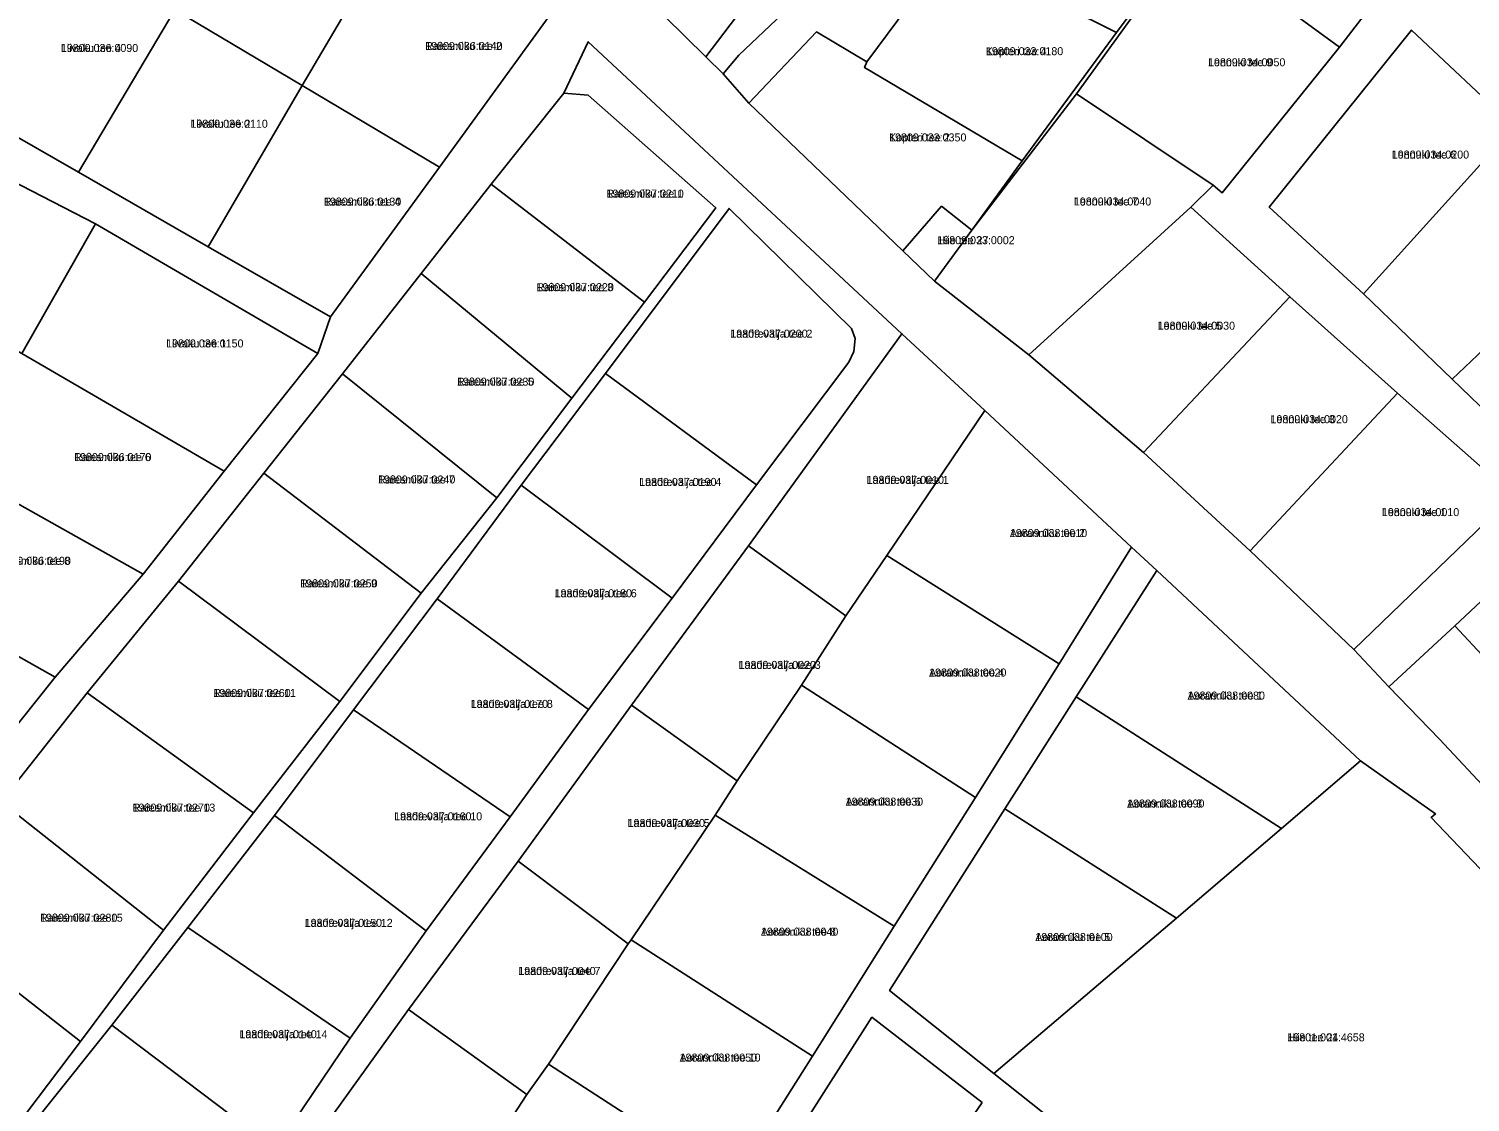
# Model space of a CAD drawing. Extents: x 516875 to 535633, y 6574491 to 6593094.
# Drawn here: x 521221.7 to 521492, y 6587952 to 6588153.3 of the extents above; entities that cross this region are included whole.
import ezdxf

# ---------------------------------------------------------------- set-up
doc = ezdxf.new("R2010")
doc.units = 0
for name, color, linetype in [('L_AADRESS', 7, 'Continuous'), ('PIIR', 7, 'Continuous'), ('TUNNUS', 7, 'Continuous')]:
    doc.layers.add(name, color=color, linetype=linetype)

msp = doc.modelspace()

# ---------------------------------------------------------------- linework, layer by layer
at = {"layer": 'PIIR'}
for points in [[(521017.6, 6588315.56), (521041.3, 6588310.85), (521161.97, 6588248.41), (521164, 6588251.13), (521249.19, 6588215.21), (521251.74, 6588208.19), (521261.65, 6588203.54), (521269.05, 6588200.08), (521301.38, 6588180.99), (521317.52, 6588171.31), (521334.28, 6588161.25), (521337.07, 6588159.57), (521348.67, 6588148.07), (521351.93, 6588144.84), (521356.73, 6588139.38), (521385.64, 6588111.65), (521391.55, 6588105.98), (521409.24, 6588092.16), (521430.76, 6588073.85), (521450.73, 6588055.41), (521470.18, 6588036.92), (521476.73, 6588029.86), (521486.21, 6588020.09), (521519.33, 6587984.61)], [(521158.93, 6587943.85), (521180.61, 6587971.98), (521193.57, 6587989.19), (521210.46, 6588011.39), (521226.67, 6588031.69), (521243.16, 6588051), (521258.36, 6588070.34), (521275.91, 6588092.39), (521278.32, 6588099.31), (521298.75, 6588127.37), (521319.09, 6588155.45), (521290.81, 6588172.96), (521266.84, 6588187.34), (521242.95, 6588201.16), (521217.86, 6588215.37), (521191.59, 6588226.05), (521158.76, 6588238.82), (521154.23, 6588241.17), (521121.69, 6588257.97), (521102.37, 6588267.78), (521050.16, 6588294.72), (521045.07, 6588297.27), (521040.82, 6588299.53), (521002.53, 6588304.56)], [(521540.83, 6588089.77), (521489.11, 6588041.31), (521476.73, 6588029.86), (521470.18, 6588036.92), (521500.13, 6588065.78), (521478.34, 6588084.96), (521458.19, 6588103.05), (521439.62, 6588119.88), (521443.81, 6588124.01), (521445.49, 6588122.56), (521467.47, 6588149.88), (521488.12, 6588176.69), (521508.12, 6588202.69)], [(521394.5, 6588168.18), (521378.85, 6588147.09), (521369.43, 6588152.73), (521356.73, 6588139.38), (521351.93, 6588144.84), (521354.89, 6588148.37), (521363.04, 6588156.13)], [(521500.27, 6588134.95), (521481, 6588153.08), (521454.29, 6588119.88), (521471.99, 6588103.62), (521488.58, 6588087.62), (521505.71, 6588071.1)], [(521514.67, 6587973.91), (521484.65, 6588005.35), (521485.51, 6588006.06), (521471.41, 6588015.99), (521433.21, 6588051.72), (521428.49, 6588056.06), (521400.98, 6588081.73), (521385.44, 6588096.11), (521326.62, 6588150.87), (521322.04, 6588141.26), (521308.43, 6588124.17), (521295.33, 6588107.43), (521280.58, 6588088.62), (521265.78, 6588069.94), (521249.81, 6588049.72), (521232.68, 6588028.77), (521216.57, 6588008.3), (521200.27, 6587987.77), (521181.69, 6587964.04), (521164.92, 6587943.01)], [(521215.28, 6587942.14), (521231.42, 6587963.35), (521246.97, 6587984.22), (521263.88, 6588006.26), (521280.05, 6588027.13), (521295.3, 6588047.44), (521309.48, 6588065.34), (521323.53, 6588084.02), (521337.18, 6588102.04), (521350.56, 6588119.72), (521326.59, 6588140.87), (521322.04, 6588141.26), (521326.62, 6588150.87), (521385.44, 6588096.11), (521356.66, 6588056.35), (521334.72, 6588026.42), (521313.46, 6587997.16), (521292.9, 6587969.35), (521274.13, 6587943.17)], [(521138.98, 6587940.98), (521137.6, 6587971.07), (521136.28, 6588000.92), (521134.56, 6588030.83), (521132.41, 6588064.75), (521158.39, 6588098), (521171.42, 6588121.81), (521183.95, 6588143.81), (521193.2, 6588147.93), (521206.39, 6588140.55), (521231.05, 6588126.44), (521255.39, 6588112.43), (521278.32, 6588099.31), (521275.91, 6588092.39), (521234.23, 6588116.76), (521190.3, 6588139.35), (521178.02, 6588117.45), (521165.86, 6588095.28), (521153.98, 6588073.57), (521141.75, 6588051.55), (521141.82, 6588020.03), (521142.39, 6587992.23), (521145.81, 6587956.49), (521147.96, 6587948.67)], [(521267.98, 6587943.22), (521281.97, 6587963.99), (521296.27, 6587984.13), (521311.97, 6588005.48), (521326.68, 6588025.64), (521342.39, 6588046.49), (521358.19, 6588067.75), (521375.48, 6588090.78), (521376.44, 6588092.78), (521376.68, 6588095.2), (521376.01, 6588097.08), (521353.02, 6588119.61), (521329.85, 6588088.65), (521314.08, 6588067.74), (521298.31, 6588046.39), (521282.64, 6588025.58), (521267.79, 6588005.75), (521251.54, 6587984.76), (521237.28, 6587966.42), (521224.36, 6587950.23)], [(521353.63, 6587936.77), (521368.68, 6587960.59), (521383.97, 6587985.03), (521399.21, 6588009.13), (521414.9, 6588034.22), (521428.49, 6588056.06), (521433.21, 6588051.72), (521418.12, 6588028.01), (521404.73, 6588007.03), (521383.13, 6587972.91), (521402.67, 6587957.39), (521442.87, 6587925.41)], [(521400.47, 6587951.9), (521379.8, 6587967.93), (521355.54, 6587929.86)]]:
    msp.add_lwpolyline(points, dxfattribs=at)
for points in [[(521488.12, 6588176.69), (521467.47, 6588149.88), (521439.37, 6588170.42), (521453.71, 6588190.56), (521459.29, 6588197.98)], [(521290.81, 6588172.96), (521273.02, 6588142.68), (521249.1, 6588156.87), (521266.84, 6588187.34)], [(521440.2, 6588172.11), (521425.69, 6588152.61), (521394.5, 6588168.18), (521409.1, 6588187.6)], [(521319.09, 6588155.45), (521298.75, 6588127.37), (521273.02, 6588142.68), (521290.81, 6588172.96)], [(521347.85, 6588171.73), (521344.77, 6588166.29), (521350.63, 6588162.97), (521353.71, 6588168.4), (521360.97, 6588164.28), (521348.67, 6588148.07), (521337.07, 6588159.57), (521334.28, 6588161.25), (521343.47, 6588173.7)], [(521249.1, 6588156.87), (521231.05, 6588126.44), (521206.39, 6588140.55), (521225.06, 6588171.18)], [(521467.47, 6588149.88), (521445.49, 6588122.56), (521443.81, 6588124.01), (521418.19, 6588141.14), (521439.37, 6588170.42)], [(521425.69, 6588152.61), (521408, 6588128.54), (521378.45, 6588146.05), (521378.85, 6588147.09), (521394.5, 6588168.18)], [(521364.05, 6588161.68), (521363.04, 6588156.13), (521354.89, 6588148.37), (521351.93, 6588144.84), (521348.67, 6588148.07), (521360.97, 6588164.28)], [(521273.02, 6588142.68), (521255.39, 6588112.43), (521231.05, 6588126.44), (521249.1, 6588156.87)], [(521378.85, 6588147.09), (521378.45, 6588146.05), (521408, 6588128.54), (521398.52, 6588115.54), (521392.87, 6588120.03), (521385.64, 6588111.65), (521356.73, 6588139.38), (521369.43, 6588152.73)], [(521500.27, 6588134.95), (521471.99, 6588103.62), (521454.29, 6588119.88), (521481, 6588153.08)], [(521298.75, 6588127.37), (521278.32, 6588099.31), (521255.39, 6588112.43), (521273.02, 6588142.68)], [(521234.23, 6588116.76), (521220.42, 6588092.43), (521218.56, 6588093.45), (521178.02, 6588117.45), (521190.3, 6588139.35)], [(521322.04, 6588141.26), (521326.59, 6588140.87), (521350.56, 6588119.72), (521337.18, 6588102.04), (521308.43, 6588124.17)], [(521443.81, 6588124.01), (521439.62, 6588119.88), (521409.24, 6588092.16), (521391.55, 6588105.98), (521398.52, 6588115.54), (521418.19, 6588141.14)], [(521506.61, 6588128.99), (521519.5, 6588116.86), (521488.58, 6588087.62), (521471.99, 6588103.62), (521500.27, 6588134.95)], [(521308.43, 6588124.17), (521337.18, 6588102.04), (521323.53, 6588084.02), (521295.33, 6588107.43)], [(521353.02, 6588119.61), (521376.01, 6588097.08), (521376.68, 6588095.2), (521376.44, 6588092.78), (521375.48, 6588090.78), (521358.19, 6588067.75), (521329.85, 6588088.65)], [(521398.52, 6588115.54), (521391.55, 6588105.98), (521385.64, 6588111.65), (521392.87, 6588120.03)], [(521458.19, 6588103.05), (521430.76, 6588073.85), (521409.24, 6588092.16), (521439.62, 6588119.88)], [(521275.91, 6588092.39), (521258.36, 6588070.34), (521220.42, 6588092.43), (521234.23, 6588116.76)], [(521537.69, 6588100.14), (521534.98, 6588097.54), (521505.71, 6588071.1), (521488.58, 6588087.62), (521519.5, 6588116.86)], [(521295.33, 6588107.43), (521323.53, 6588084.02), (521309.48, 6588065.34), (521280.58, 6588088.62)], [(521478.34, 6588084.96), (521450.73, 6588055.41), (521430.76, 6588073.85), (521458.19, 6588103.05)], [(521356.66, 6588056.35), (521385.44, 6588096.11), (521400.98, 6588081.73), (521382.59, 6588054.52), (521374.93, 6588043.23)], [(521220.42, 6588092.43), (521258.36, 6588070.34), (521243.16, 6588051), (521204.84, 6588072.5), (521218.56, 6588093.45)], [(521280.58, 6588088.62), (521309.48, 6588065.34), (521295.3, 6588047.44), (521265.78, 6588069.94)], [(521329.85, 6588088.65), (521358.19, 6588067.75), (521342.39, 6588046.49), (521314.08, 6588067.74)], [(521489.11, 6588041.31), (521540.83, 6588089.77), (521552.09, 6588077.21), (521557.57, 6588080.35), (521576.42, 6588072.76), (521587.8, 6588066.87), (521550.43, 6588019.97), (521539.48, 6588031.44), (521535.42, 6588027.5), (521529.37, 6588027.23), (521500.98, 6588028.57)], [(521500.13, 6588065.78), (521470.18, 6588036.92), (521450.73, 6588055.41), (521478.34, 6588084.96)], [(521428.49, 6588056.06), (521414.9, 6588034.22), (521382.59, 6588054.52), (521400.98, 6588081.73)], [(521204.84, 6588072.5), (521243.16, 6588051), (521226.67, 6588031.69), (521190.03, 6588052.36), (521202.42, 6588073.87)], [(521265.78, 6588069.94), (521295.3, 6588047.44), (521280.05, 6588027.13), (521249.81, 6588049.72)], [(521314.08, 6588067.74), (521342.39, 6588046.49), (521326.68, 6588025.64), (521298.31, 6588046.39)], [(521334.72, 6588026.42), (521356.66, 6588056.35), (521374.93, 6588043.23), (521366.64, 6588030.18), (521354.56, 6588012.25)], [(521414.9, 6588034.22), (521399.21, 6588009.13), (521366.64, 6588030.18), (521374.93, 6588043.23), (521382.59, 6588054.52)], [(521226.67, 6588031.69), (521210.46, 6588011.39), (521180.01, 6588029.19), (521177.09, 6588030.93), (521190.03, 6588052.36)], [(521471.41, 6588015.99), (521456.62, 6588003.29), (521418.12, 6588028.01), (521433.21, 6588051.72)], [(521249.81, 6588049.72), (521280.05, 6588027.13), (521263.88, 6588006.26), (521232.68, 6588028.77)], [(521298.31, 6588046.39), (521326.68, 6588025.64), (521311.97, 6588005.48), (521282.64, 6588025.58)], [(521476.73, 6588029.86), (521489.11, 6588041.31), (521500.98, 6588028.57), (521529.37, 6588027.23), (521535.42, 6588027.5), (521539.48, 6588031.44), (521550.43, 6588019.97), (521519.33, 6587984.61), (521486.21, 6588020.09)], [(521232.68, 6588028.77), (521263.88, 6588006.26), (521246.97, 6587984.22), (521216.57, 6588008.3)], [(521399.21, 6588009.13), (521383.97, 6587985.03), (521350.41, 6588005.82), (521354.56, 6588012.25), (521366.64, 6588030.18)], [(521334.72, 6588026.42), (521354.56, 6588012.25), (521350.41, 6588005.82), (521334.68, 6587982.43), (521334.13, 6587981.66), (521313.46, 6587997.16)], [(521456.62, 6588003.29), (521436.92, 6587986.49), (521404.73, 6588007.03), (521418.12, 6588028.01)], [(521282.64, 6588025.58), (521311.97, 6588005.48), (521296.27, 6587984.13), (521267.79, 6588005.75)], [(521456.62, 6588003.29), (521471.41, 6588015.99), (521485.51, 6588006.06), (521484.65, 6588005.35), (521514.67, 6587973.91), (521492.26, 6587947.79), (521477.81, 6587930.85), (521464.56, 6587914.78), (521461.03, 6587910.82), (521442.87, 6587925.41), (521402.67, 6587957.39), (521436.92, 6587986.49)], [(521216.57, 6588008.3), (521246.97, 6587984.22), (521231.42, 6587963.35), (521200.27, 6587987.77)], [(521436.92, 6587986.49), (521402.67, 6587957.39), (521383.13, 6587972.91), (521404.73, 6588007.03)], [(521267.79, 6588005.75), (521296.27, 6587984.13), (521281.97, 6587963.99), (521251.54, 6587984.76)], [(521383.97, 6587985.03), (521368.68, 6587960.59), (521334.68, 6587982.43), (521350.41, 6588005.82)], [(521313.46, 6587997.16), (521334.13, 6587981.66), (521319.16, 6587959.1), (521315.09, 6587953.45), (521292.9, 6587969.35)], [(521200.27, 6587987.77), (521231.42, 6587963.35), (521215.28, 6587942.14), (521181.69, 6587964.04)], [(521251.54, 6587984.76), (521281.97, 6587963.99), (521267.98, 6587943.22), (521237.28, 6587966.42)], [(521368.68, 6587960.59), (521353.63, 6587936.77), (521319.16, 6587959.1), (521334.13, 6587981.66), (521334.68, 6587982.43)], [(521292.9, 6587969.35), (521315.09, 6587953.45), (521303.38, 6587935.38), (521297.34, 6587926.82), (521274.13, 6587943.17)], [(521224.36, 6587950.23), (521237.28, 6587966.42), (521267.98, 6587943.22), (521254.61, 6587924.08), (521223.14, 6587947.9)], [(521400.47, 6587951.9), (521375.09, 6587915), (521355.54, 6587929.86), (521379.8, 6587967.93)], [(521353.63, 6587936.77), (521339.07, 6587913.66), (521303.38, 6587935.38), (521315.09, 6587953.45), (521319.16, 6587959.1)]]:
    msp.add_lwpolyline(points, close=True, dxfattribs=at)

# ---------------------------------------------------------------- texts
at = {"layer": 'L_AADRESS'}
for s, p in [('Liivaku tee 4', (521227.75, 6588148.96)), ('Raiesmiku tee 2', (521296.06, 6588149.34)), ('Kopteri tee 4', (521401.18, 6588148.36)), ('Lennuki tee 9', (521442.83, 6588146.28)), ('Liivaku tee 2', (521252.04, 6588134.75)), ('Kopteri tee 2', (521383.03, 6588132.19)), ('Lennuki tee 6', (521477.28, 6588128.97)), ('Raiesmiku tee 1', (521330.04, 6588121.65)), ('Raiesmiku tee 4', (521277.07, 6588120.15)), ('Lennuki tee 7', (521417.68, 6588120.17)), ('Hiie tee 27', (521392.08, 6588112.91)), ('Raiesmiku tee 3', (521316.93, 6588104.1)), ('Laadrevälja tee 2', (521353.27, 6588095.38)), ('Lennuki tee 5', (521433.39, 6588096.87)), ('Liivaku tee 1', (521247.49, 6588093.55)), ('Raiesmiku tee 5', (521302.02, 6588086.38)), ('Lennuki tee 3', (521454.55, 6588079.34)), ('Raiesmiku tee 6', (521230.23, 6588072.23)), ('Raiesmiku tee 7', (521287.21, 6588068.03)), ('Laadrevälja tee 4', (521336.18, 6588067.57)), ('Laadrevälja tee 1', (521378.82, 6588067.96)), ('Lennuki tee 1', (521475.43, 6588061.91)), ('Aoranniku tee 2', (521405.68, 6588057.98)), ('Raiesmiku tee 8', (521215.13, 6588052.78)), ('Raiesmiku tee 9', (521272.63, 6588048.54)), ('Laadrevälja tee 6', (521320.33, 6588046.69)), ('Laadrevälja tee 3', (521354.82, 6588033.25)), ('Aoranniku tee 4', (521390.54, 6588031.82)), ('Raiesmiku tee 11', (521256.33, 6588027.99)), ('Aoranniku tee 1', (521439, 6588027.5)), ('Laadrevälja tee 8', (521304.59, 6588025.94)), ('Raiesmiku tee 13', (521241.2, 6588006.49)), ('Aoranniku tee 6', (521374.9, 6588007.61)), ('Aoranniku tee 3', (521427.66, 6588007.25)), ('Laadrevälja tee 10', (521290.24, 6588004.85)), ('Laadrevälja tee 5', (521334.01, 6588003.6)), ('Raiesmiku tee 15', (521223.85, 6587985.83)), ('Laadrevälja tee 12', (521273.46, 6587984.87)), ('Aoranniku tee 8', (521359.01, 6587983.21)), ('Aoranniku tee 5', (521410.45, 6587982.21)), ('Laadrevälja tee 7', (521313.52, 6587975.85)), ('Laadrevälja tee 14', (521261.23, 6587963.99)), ('Hiie tee 24', (521457.7, 6587963.4)), ('Aoranniku tee 10', (521343.77, 6587959.6))]:
    msp.add_text(s, height=1.5, dxfattribs=at).set_placement(p)
at = {"layer": 'TUNNUS'}
for s, p in [('19809:036:0090', (521227.75, 6588148.96)), ('19809:036:0140', (521296.06, 6588149.34)), ('19809:033:0180', (521401.18, 6588148.36)), ('19809:034:0050', (521442.83, 6588146.28)), ('19809:036:0110', (521252.04, 6588134.75)), ('19809:033:0350', (521383.03, 6588132.19)), ('19809:034:0200', (521477.28, 6588128.97)), ('19809:037:0210', (521330.04, 6588121.65)), ('19809:036:0130', (521277.07, 6588120.15)), ('19809:034:0040', (521417.68, 6588120.17)), ('19809:033:0002', (521392.08, 6588112.91)), ('19809:037:0220', (521316.93, 6588104.1)), ('19809:037:0200', (521353.27, 6588095.38)), ('19809:034:0030', (521433.39, 6588096.87)), ('19809:036:0150', (521247.49, 6588093.55)), ('19809:037:0230', (521302.02, 6588086.38)), ('19809:034:0020', (521454.55, 6588079.34)), ('19809:036:0170', (521230.23, 6588072.23)), ('19809:037:0240', (521287.21, 6588068.03)), ('19809:037:0190', (521336.18, 6588067.57)), ('19809:037:0010', (521378.82, 6588067.96)), ('19809:034:0010', (521475.43, 6588061.91)), ('19809:038:0010', (521405.68, 6588057.98)), ('19809:036:0190', (521215.13, 6588052.78)), ('19809:037:0250', (521272.63, 6588048.54)), ('19809:037:0180', (521320.33, 6588046.69)), ('19809:037:0020', (521354.82, 6588033.25)), ('19809:038:0020', (521390.54, 6588031.82)), ('19809:037:0260', (521256.33, 6588027.99)), ('19809:038:0080', (521439, 6588027.5)), ('19809:037:0170', (521304.59, 6588025.94)), ('19809:037:0270', (521241.2, 6588006.49)), ('19809:038:0030', (521374.9, 6588007.61)), ('19809:038:0090', (521427.66, 6588007.25)), ('19809:037:0160', (521290.24, 6588004.85)), ('19809:037:0030', (521334.01, 6588003.6)), ('19809:037:0280', (521223.85, 6587985.83)), ('19809:037:0150', (521273.46, 6587984.87)), ('19809:038:0040', (521359.01, 6587983.21)), ('19809:038:0100', (521410.45, 6587982.21)), ('19809:037:0040', (521313.52, 6587975.85)), ('19809:037:0140', (521261.23, 6587963.99)), ('19801:001:4658', (521457.7, 6587963.4)), ('19809:038:0050', (521343.77, 6587959.6))]:
    msp.add_text(s, height=1.5, dxfattribs=at).set_placement(p)

doc.saveas('drawing.dxf')
